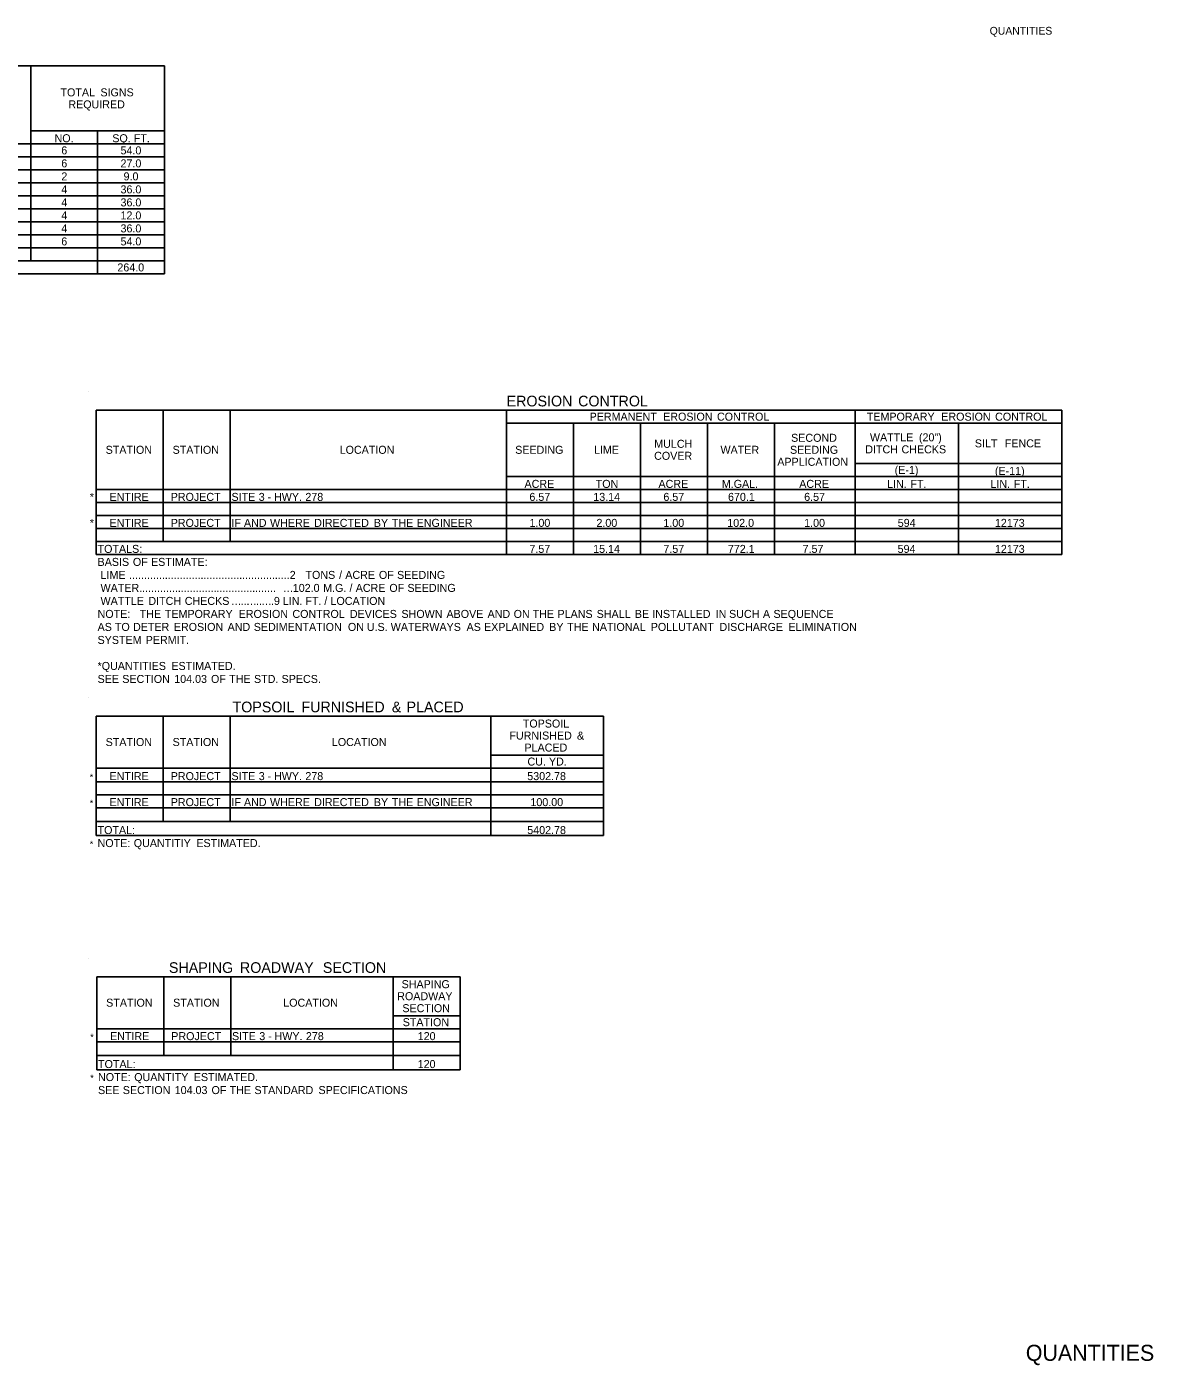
# Model space of a CAD drawing. Extents: x 925 to 1648, y 318 to 522.
# Drawn here: x 1043.4 to 1212.3, y 318.1 to 518.8 of the extents above; entities that cross this region are included whole.
import ezdxf

# ---------------------------------------------------------------- set-up
doc = ezdxf.new("R2010")
doc.units = 0
for name, color, linetype in [('Default', 7, 'Continuous'), ('R_Annotation', 7, 'Continuous'), ('R_Border', 7, 'Continuous'), ('R_Border Prem', 7, 'Continuous')]:
    doc.layers.add(name, color=color, linetype=linetype)

msp = doc.modelspace()

# ---------------------------------------------------------------- linework, layer by layer
at = {"layer": 'Default'}
for p, q in [((928.68, 512.98), (1064.11, 512.98)), ((1044.03, 483.73), (1044.03, 512.98)), ((1064.11, 481.78), (1064.11, 512.98)), ((1064.11, 481.78), (1064.11, 512.98)), ((1044.03, 503.23), (1064.11, 503.23)), ((1054.07, 481.78), (1054.07, 503.23)), ((928.68, 501.28), (1064.11, 501.28)), ((1032.42, 501.28), (1064.11, 501.28)), ((1054.07, 481.78), (1054.07, 501.28)), ((928.68, 499.33), (1064.11, 499.33)), ((928.68, 497.38), (1064.11, 497.38)), ((928.68, 495.43), (1064.11, 495.43)), ((928.68, 493.48), (1064.11, 493.48)), ((928.68, 491.53), (1064.11, 491.53)), ((928.68, 489.58), (1064.11, 489.58)), ((928.68, 487.63), (1064.11, 487.63)), ((928.68, 485.68), (1064.11, 485.68)), ((928.68, 483.73), (1064.11, 483.73)), ((928.68, 481.78), (1064.11, 481.78)), ((1053.86, 461.35), (1198.65, 461.35)), ((1053.86, 439.7), (1053.86, 461.35)), ((1053.86, 439.7), (1053.86, 461.35)), ((1063.91, 441.65), (1063.91, 461.35)), ((1073.95, 441.65), (1073.95, 461.35)), ((1115.39, 439.7), (1115.39, 461.35)), ((1167.65, 439.7), (1167.65, 461.35)), ((1167.65, 459.4), (1167.65, 461.35)), ((1198.65, 459.4), (1198.65, 461.35)), ((1198.65, 439.7), (1198.65, 461.35)), ((1115.39, 459.4), (1198.65, 459.4)), ((1125.43, 439.7), (1125.43, 459.4)), ((1135.47, 439.7), (1135.47, 459.4)), ((1145.51, 439.7), (1145.51, 459.4)), ((1155.56, 439.7), (1155.56, 459.4)), ((1183.15, 439.7), (1183.15, 459.4)), ((1167.65, 453.35), (1198.65, 453.35)), ((1115.39, 451.4), (1198.65, 451.4)), ((1125.43, 439.7), (1125.43, 451.4)), ((1135.47, 441.65), (1135.47, 451.4)), ((1145.51, 441.65), (1145.51, 451.4)), ((1155.56, 449.45), (1155.56, 451.4)), ((1167.65, 449.45), (1167.65, 451.4)), ((1183.15, 449.45), (1183.15, 451.4)), ((1198.65, 439.7), (1198.65, 451.4)), ((1053.86, 449.45), (1198.65, 449.45)), ((1063.91, 441.65), (1063.91, 449.45)), ((1073.95, 441.65), (1073.95, 449.45)), ((1115.39, 439.7), (1115.39, 449.45)), ((1053.86, 447.5), (1198.65, 447.5)), ((1053.86, 445.55), (1198.65, 445.55)), ((1053.86, 443.6), (1198.65, 443.6)), ((1053.86, 441.65), (1155.56, 441.65)), ((1053.86, 441.65), (1145.51, 441.65)), ((1145.51, 441.65), (1198.65, 441.65)), ((1053.86, 439.7), (1198.65, 439.7)), ((1053.86, 415.48), (1129.91, 415.48)), ((1053.86, 397.54), (1053.86, 415.48)), ((1053.86, 397.54), (1053.86, 415.48)), ((1063.91, 399.68), (1063.91, 415.48)), ((1073.95, 399.68), (1073.95, 415.48)), ((1113.05, 397.54), (1113.05, 415.48)), ((1129.91, 397.54), (1129.91, 415.48)), ((1129.91, 397.54), (1129.91, 415.48)), ((1113.05, 409.63), (1129.91, 409.63)), ((1053.86, 407.68), (1129.91, 407.68)), ((1063.91, 399.68), (1063.91, 407.68)), ((1073.95, 399.68), (1073.95, 407.68)), ((1113.05, 397.54), (1113.05, 407.68)), ((1053.86, 405.63), (1129.91, 405.63)), ((1113.05, 405.63), (1129.91, 405.63)), ((1053.86, 403.68), (1129.91, 403.68)), ((1053.86, 401.73), (1129.91, 401.73)), ((1053.86, 399.68), (1063.91, 399.68)), ((1053.86, 399.68), (1129.91, 399.68)), ((1063.91, 399.68), (1073.95, 399.68)), ((1073.95, 399.68), (1113.05, 399.68)), ((1053.86, 397.54), (1129.91, 397.54)), ((1053.94, 376.39), (1108.44, 376.39)), ((1053.94, 362.45), (1053.94, 376.39)), ((1053.94, 362.45), (1053.94, 376.39)), ((1063.98, 364.59), (1063.98, 376.39)), ((1074.02, 364.59), (1074.02, 376.39)), ((1098.4, 362.45), (1098.4, 376.39)), ((1108.44, 362.45), (1108.44, 376.39)), ((1108.44, 362.45), (1108.44, 376.39)), ((1098.4, 370.54), (1108.44, 370.54)), ((1053.94, 368.59), (1108.44, 368.59)), ((1063.98, 364.59), (1063.98, 368.59)), ((1074.02, 364.59), (1074.02, 368.59)), ((1098.4, 362.45), (1098.4, 368.59)), ((1053.94, 366.64), (1108.44, 366.64)), ((1053.94, 364.59), (1108.44, 364.59)), ((1053.94, 364.59), (1108.44, 364.59)), ((1053.94, 362.45), (1108.44, 362.45))]:
    msp.add_line(p, q, dxfattribs=at)
at = {"layer": 'R_Border Prem'}
for p, q in [((1052.69, 464.08), (1052.69, 464.08)), ((1052.69, 418.21), (1052.69, 418.21)), ((1052.77, 379.12), (1052.77, 379.12))]:
    msp.add_line(p, q, dxfattribs=at)

# ---------------------------------------------------------------- texts
at = {"layer": 'Default'}
for s, height, p in [('TOTAL', 1.2, (1048.5, 508.4)), ('REQUIRED', 1.2, (1049.68, 506.6)), (' SIGNS', 1.2, (1054.04, 508.4)), ('NO.', 1.2, (1047.61, 501.52)), ('SQ.', 1.2, (1056.27, 501.52)), (' FT.', 1.2, (1059.04, 501.52)), ('6', 1.2, (1048.62, 499.7)), ('54.0', 1.2, (1057.5, 499.7)), ('6', 1.2, (1048.62, 497.75)), ('27.0', 1.2, (1057.5, 497.75)), ('2', 1.2, (1048.63, 495.8)), ('9.0', 1.2, (1057.96, 495.8)), ('4', 1.2, (1048.62, 493.85)), ('36.0', 1.2, (1057.5, 493.85)), ('4', 1.2, (1048.62, 491.9)), ('36.0', 1.2, (1057.5, 491.9)), ('4', 1.2, (1048.62, 489.95)), ('12.0', 1.2, (1057.5, 489.95)), ('4', 1.2, (1048.62, 488)), ('36.0', 1.2, (1057.5, 488)), ('6', 1.2, (1048.62, 486.05)), ('54.0', 1.2, (1057.5, 486.05)), ('264.0', 1.2, (1057.03, 482.15)), ('EROSION', 1.6, (1115.39, 461.91)), (' CONTROL', 1.6, (1125.52, 461.91)), ('PERMANENT', 1.2, (1127.84, 459.77)), (' EROSION', 1.2, (1138.42, 459.77)), (' CONTROL', 1.2, (1146.49, 459.77)), ('TEMPORARY', 1.2, (1169.4, 459.77)), (' EROSION', 1.2, (1180.12, 459.77)), (' CONTROL', 1.2, (1188.19, 459.77)), ('SECOND', 1.2, (1158.05, 456.6)), ('WATTLE', 1.2, (1169.87, 456.67)), (' (20")', 1.2, (1176.77, 456.67)), ('STATION', 1.2, (1055.27, 454.8)), ('STATION', 1.2, (1065.31, 454.8)), ('LOCATION', 1.2, (1090.36, 454.8)), ('SEEDING', 1.2, (1116.68, 454.8)), ('LIME', 1.2, (1128.49, 454.8)), ('MULCH', 1.2, (1137.53, 455.7)), ('WATER', 1.2, (1147.46, 454.8)), ('SEEDING', 1.2, (1157.88, 454.8)), ('DITCH', 1.2, (1169.17, 454.87)), (' CHECKS', 1.2, (1174.16, 454.87)), ('SILT', 1.2, (1185.6, 455.77)), ('  FENCE', 1.2, (1189.2, 455.77)), ('COVER', 1.2, (1137.51, 453.9)), ('APPLICATION', 1.2, (1155.98, 453)), ('(E-1)', 1.2, (1173.58, 451.78)), ('(E-11)', 1.2, (1188.61, 451.64)), ('ACRE', 1.2, (1118.07, 449.69)), ('TON', 1.2, (1128.75, 449.69)), ('ACRE', 1.2, (1138.16, 449.69)), ('M.GAL.', 1.2, (1147.66, 449.69)), ('ACRE', 1.2, (1159.27, 449.69)), ('LIN.', 1.2, (1172.44, 449.69)), (' FT.', 1.2, (1175.49, 449.69)), ('LIN.', 1.2, (1187.94, 449.69)), (' FT.', 1.2, (1190.99, 449.69)), ('*', 1.2, (1052.89, 447.74)), ('ENTIRE', 1.2, (1055.85, 447.74)), ('PROJECT', 1.2, (1065.03, 447.74)), ('SITE', 1.2, (1074.14, 447.74)), (' 3', 1.2, (1077.78, 447.74)), (' -', 1.2, (1079.1, 447.74)), (' HWY.', 1.2, (1080.07, 447.74)), (' 278', 1.2, (1084.77, 447.74)), ('6.57', 1.2, (1118.81, 447.74)), ('13.14', 1.2, (1128.39, 447.74)), ('6.57', 1.2, (1138.9, 447.74)), ('670.1', 1.2, (1148.59, 447.74)), ('6.57', 1.2, (1160.01, 447.74)), ('*', 1.2, (1052.89, 443.84)), ('ENTIRE', 1.2, (1055.85, 443.84)), ('PROJECT', 1.2, (1065.03, 443.84)), ('IF', 1.2, (1074.14, 443.84)), (' AND', 1.2, (1075.56, 443.84)), (' WHERE', 1.2, (1079.47, 443.84)), (' DIRECTED', 1.2, (1086.09, 443.84)), (' BY', 1.2, (1095.04, 443.84)), (' THE', 1.2, (1097.73, 443.84)), (' ENGINEER', 1.2, (1101.46, 443.84)), ('1.00', 1.2, (1118.82, 443.84)), ('2.00', 1.2, (1128.86, 443.84)), ('1.00', 1.2, (1138.9, 443.84)), ('102.0', 1.2, (1148.48, 443.84)), ('1.00', 1.2, (1160.01, 443.84)), ('594', 1.2, (1174.04, 443.84)), ('12173', 1.2, (1188.61, 443.84)), ('TOTALS:', 1.2, (1054.06, 439.94)), ('7.57', 1.2, (1118.81, 439.94)), ('15.14', 1.2, (1128.37, 439.94)), ('7.57', 1.2, (1138.9, 439.94)), ('772.1', 1.2, (1148.57, 439.94)), ('7.57', 1.2, (1159.77, 439.94)), ('594', 1.2, (1174.02, 439.94)), ('12173', 1.2, (1188.61, 439.94)), ('BASIS', 1.2, (1054.06, 437.99)), (' OF', 1.2, (1058.91, 437.99)), (' ESTIMATE:', 1.2, (1061.63, 437.99)), (' LIME', 1.2, (1054.06, 436.04)), (' ......................................................2', 1.2, (1058.35, 436.04)), (' TONS', 1.2, (1084.79, 436.04)), (' /', 1.2, (1089.83, 436.04)), (' ACRE', 1.2, (1090.76, 436.04)), (' OF', 1.2, (1095.8, 436.04)), (' SEEDING', 1.2, (1098.52, 436.04)), (' WATER..............................................', 1.2, (1054.06, 434.09)), ('…', 1.2, (1081.85, 434.09)), ('102.0', 1.2, (1083.33, 434.09)), (' M.G.', 1.2, (1087.44, 434.09)), (' /', 1.2, (1091.39, 434.09)), (' ACRE', 1.2, (1092.32, 434.09)), (' OF', 1.2, (1097.36, 434.09)), (' SEEDING', 1.2, (1100.08, 434.09)), (' WATTLE', 1.2, (1054.06, 432.14)), (' DITCH', 1.2, (1061.23, 432.14)), (' CHECKS', 1.2, (1066.69, 432.14)), ('…', 1.2, (1074.05, 432.14)), ('..', 1.2, (1075.53, 432.14)), ('…', 1.2, (1076.32, 432.14)), ('..', 1.2, (1077.8, 432.14)), ('…', 1.2, (1078.58, 432.14)), ('.9', 1.2, (1080.06, 432.14)), (' LIN.', 1.2, (1081.39, 432.14)), (' FT.', 1.2, (1084.78, 432.14)), (' /', 1.2, (1087.61, 432.14)), (' LOCATION', 1.2, (1088.54, 432.14)), ('NOTE:', 1.2, (1054.06, 430.19)), ('   THE', 1.2, (1059.04, 430.19)), (' TEMPORARY', 1.2, (1063.7, 430.19)), (' EROSION', 1.2, (1074.77, 430.19)), (' CONTROL', 1.2, (1082.83, 430.19)), (' DEVICES', 1.2, (1091.44, 430.19)), (' SHOWN', 1.2, (1099.18, 430.19)), (' ABOVE', 1.2, (1105.93, 430.19)), (' AND', 1.2, (1112.09, 430.19)), (' ON', 1.2, (1116, 430.19)), (' THE', 1.2, (1118.85, 430.19)), (' PLANS', 1.2, (1122.58, 430.19)), (' SHALL', 1.2, (1128.45, 430.19)), (' BE', 1.2, (1134.17, 430.19)), (' INSTALLED', 1.2, (1136.78, 430.19)), (' IN', 1.2, (1146.29, 430.19)), (' SUCH', 1.2, (1148.3, 430.19)), (' A', 1.2, (1153.38, 430.19)), (' SEQUENCE', 1.2, (1154.96, 430.19)), ('AS', 1.2, (1054.06, 428.24)), ('SYSTEM', 1.2, (1054.06, 426.29)), (' TO', 1.2, (1056.21, 428.24)), (' DETER', 1.2, (1058.93, 428.24)), (' EROSION', 1.2, (1065.05, 428.24)), (' AND', 1.2, (1073.11, 428.24)), (' SEDIMENTATION', 1.2, (1077.03, 428.24)), (' ON', 1.2, (1091.15, 428.24)), (' U.S.', 1.2, (1093.99, 428.24)), (' WATERWAYS', 1.2, (1097.57, 428.24)), (' AS', 1.2, (1108.94, 428.24)), (' EXPLAINED', 1.2, (1111.56, 428.24)), (' BY', 1.2, (1121.34, 428.24)), (' THE', 1.2, (1124.03, 428.24)), (' NATIONAL', 1.2, (1127.76, 428.24)), (' POLLUTANT', 1.2, (1136.56, 428.24)), (' DISCHARGE', 1.2, (1146.86, 428.24)), (' ELIMINATION', 1.2, (1157.21, 428.24)), (' PERMIT.', 1.2, (1060.83, 426.29)), ('*QUANTITIES', 1.2, (1054.06, 422.39)), (' ESTIMATED.', 1.2, (1064.68, 422.39)), ('SEE', 1.2, (1054.06, 420.44)), (' SECTION', 1.2, (1057.32, 420.44)), (' 104.03', 1.2, (1065.11, 420.44)), (' OF', 1.2, (1070.62, 420.44)), (' THE', 1.2, (1073.34, 420.44)), (' STD.', 1.2, (1077.07, 420.44)), (' SPECS.', 1.2, (1081.21, 420.44)), ('TOPSOIL', 1.6, (1074.29, 416.04)), (' FURNISHED', 1.6, (1084.03, 416.04)), (' &', 1.6, (1097.59, 416.04)), (' PLACED', 1.6, (1099.79, 416.04)), ('TOPSOIL', 1.2, (1117.82, 413.75)), ('STATION', 1.2, (1055.27, 410.98)), ('STATION', 1.2, (1065.31, 410.98)), ('LOCATION', 1.2, (1089.19, 410.98)), ('FURNISHED', 1.2, (1115.81, 411.95)), (' &', 1.2, (1125.5, 411.95)), ('PLACED', 1.2, (1118.07, 410.15)), ('CU.', 1.2, (1118.52, 408.05)), (' YD.', 1.2, (1121.29, 408.05)), ('*', 1, (1052.89, 405.83)), ('ENTIRE', 1.2, (1055.85, 405.87)), ('PROJECT', 1.2, (1065.03, 405.87)), ('SITE', 1.2, (1074.14, 405.87)), (' 3', 1.2, (1077.78, 405.87)), (' -', 1.2, (1079.1, 405.87)), (' HWY.', 1.2, (1080.07, 405.87)), (' 278', 1.2, (1084.77, 405.87)), ('5302.78', 1.2, (1118.49, 405.87)), ('*', 1, (1052.89, 401.93)), ('ENTIRE', 1.2, (1055.85, 401.97)), ('PROJECT', 1.2, (1065.03, 401.97)), ('IF', 1.2, (1074.14, 401.97)), (' AND', 1.2, (1075.56, 401.97)), (' WHERE', 1.2, (1079.47, 401.97)), (' DIRECTED', 1.2, (1086.09, 401.97)), (' BY', 1.2, (1095.04, 401.97)), (' THE', 1.2, (1097.73, 401.97)), (' ENGINEER', 1.2, (1101.46, 401.97)), ('100.00', 1.2, (1118.96, 401.97)), ('TOTAL:', 1.2, (1054.06, 397.78)), ('5402.78', 1.2, (1118.49, 397.78)), ('*', 1, (1052.89, 395.79)), ('NOTE:', 1.2, (1054.06, 395.83)), (' QUANTITIY', 1.2, (1059.04, 395.83)), (' ESTIMATED.', 1.2, (1068.43, 395.83)), ('SHAPING', 1.6, (1064.76, 376.96)), (' ROADWAY', 1.6, (1074.81, 376.96)), (' SECTION', 1.6, (1087.24, 376.96)), ('SHAPING', 1.2, (1099.65, 374.67)), ('ROADWAY', 1.2, (1098.99, 372.87)), ('STATION', 1.2, (1055.35, 371.89)), ('STATION', 1.2, (1065.39, 371.89)), ('LOCATION', 1.2, (1081.9, 371.89)), ('SECTION', 1.2, (1099.76, 371.07)), ('STATION', 1.2, (1099.81, 368.97)), ('*', 1, (1052.96, 366.84)), ('ENTIRE', 1.2, (1055.93, 366.88)), ('PROJECT', 1.2, (1065.11, 366.88)), ('SITE', 1.2, (1074.22, 366.88)), (' 3', 1.2, (1077.86, 366.88)), (' -', 1.2, (1079.18, 366.88)), (' HWY.', 1.2, (1080.15, 366.88)), (' 278', 1.2, (1084.85, 366.88)), ('120', 1.2, (1102.06, 366.88)), ('TOTAL:', 1.2, (1054.13, 362.69)), ('120', 1.2, (1102.06, 362.69)), ('*', 1, (1052.96, 360.7)), ('NOTE:', 1.2, (1054.13, 360.74)), (' QUANTITY', 1.2, (1059.11, 360.74)), (' ESTIMATED.', 1.2, (1068.04, 360.74)), ('SEE', 1.2, (1054.13, 358.79)), (' SECTION', 1.2, (1057.4, 358.79)), (' 104.03', 1.2, (1065.18, 358.79)), (' OF', 1.2, (1070.7, 358.79)), (' THE', 1.2, (1073.41, 358.79)), (' STANDARD', 1.2, (1077.14, 358.79)), (' SPECIFICATIONS', 1.2, (1086.74, 358.79))]:
    msp.add_text(s, height=height, dxfattribs=at).set_placement(p)
at = {"layer": 'R_Annotation'}
msp.add_text('QUANTITIES', height=2.4, dxfattribs=at).set_placement((1193.24, 318.79))
at = {"layer": 'R_Border'}
msp.add_text('QUANTITIES', height=1.17, rotation=360, dxfattribs=at).set_placement((1187.82, 517.65))

doc.saveas('drawing.dxf')
